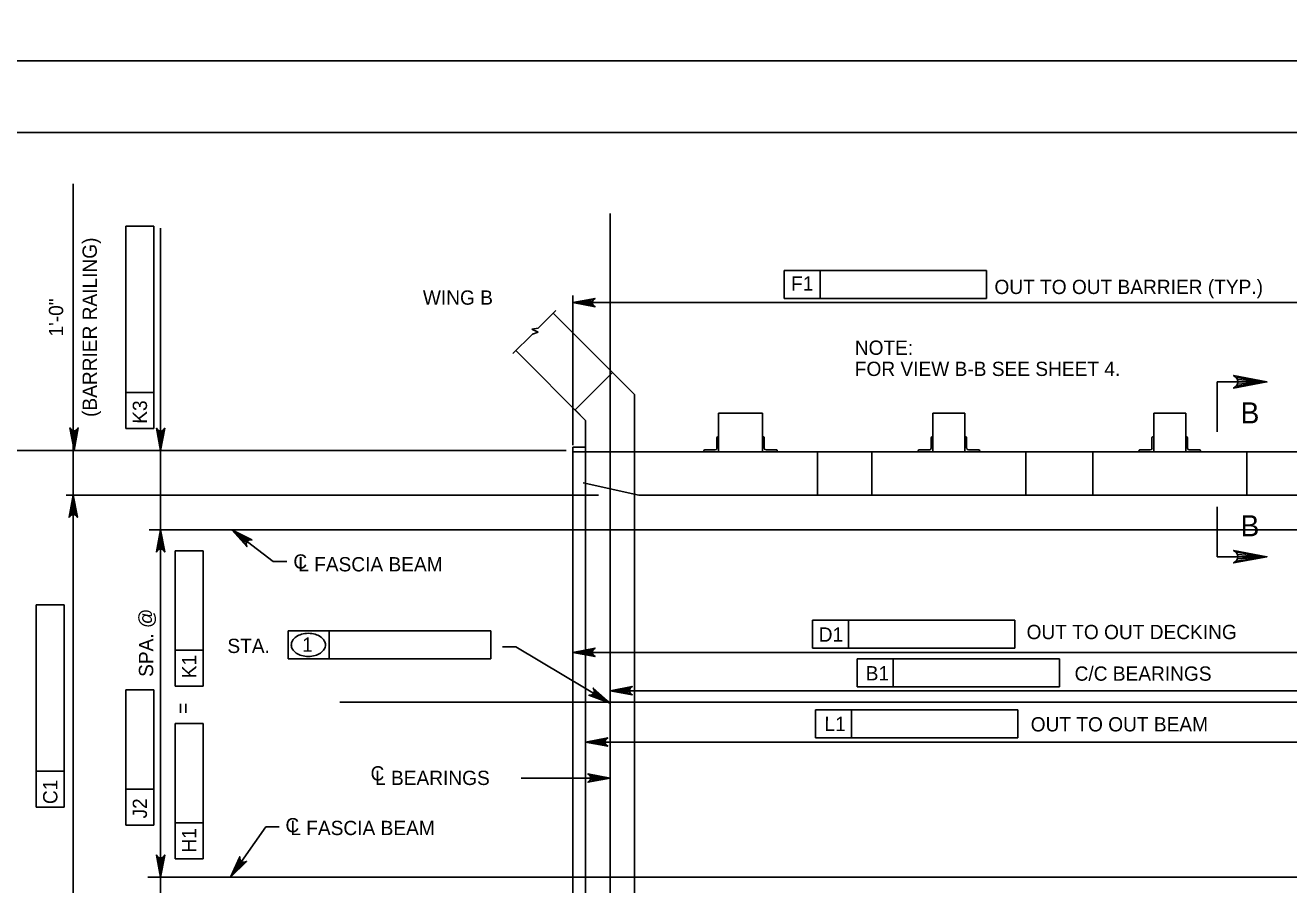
# Model space of a CAD drawing. Extents: x 638263 to 640391, y 293683 to 298655.
# Drawn here: x 638498.6 to 638763.9, y 294698.5 to 294879 of the extents above; entities that cross this region are included whole.
import ezdxf

# ---------------------------------------------------------------- set-up
doc = ezdxf.new("R2010")
doc.units = 0
for name, color, linetype in [('2', 7, 'Continuous'), ('3', 7, 'Continuous'), ('4', 7, 'Continuous'), ('PLT-BNDY', 7, 'Continuous')]:
    doc.layers.add(name, color=color, linetype=linetype)

msp = doc.modelspace()

# ---------------------------------------------------------------- linework, layer by layer
at = {"layer": '2'}
for p, q in [((638475.46, 294856.46), (639261.46, 294856.46)), ((638626.57, 294801.41), (638609.48, 294818.49)), ((638616.27, 294795.97), (638601.61, 294810.62)), ((638614.07, 294798.17), (638621.94, 294806.04)), ((638748.83, 294804.07), (638748.83, 294793.58)), ((638748.83, 294804.07), (638759.31, 294804.07)), ((638626.57, 294801.41), (638626.57, 294789.4)), ((638616.27, 294795.97), (638614.07, 294798.17)), ((638644.19, 294797.49), (638653.42, 294797.49)), ((638644.19, 294797.49), (638644.19, 294789.4)), ((638653.42, 294797.49), (638653.42, 294789.4)), ((638695.91, 294797.49), (638689.18, 294797.49)), ((638689.18, 294797.49), (638689.18, 294789.4)), ((638695.91, 294797.49), (638695.91, 294789.4)), ((638742.27, 294797.49), (638735.54, 294797.49)), ((638735.54, 294797.49), (638735.54, 294789.4)), ((638742.27, 294797.49), (638742.27, 294789.4)), ((638616.27, 294789.4), (638616.27, 294795.97)), ((638643.82, 294792.31), (638643.82, 294790.13)), ((638644, 294792.49), (638644.19, 294792.49)), ((638644.19, 294792.49), (638644.19, 294789.4)), ((638653.6, 294792.49), (638653.42, 294792.49)), ((638653.42, 294792.49), (638653.42, 294789.4)), ((638653.79, 294792.31), (638653.79, 294790.13)), ((638688.82, 294792.31), (638688.82, 294790.13)), ((638689, 294792.49), (638689.18, 294792.49)), ((638689.18, 294792.49), (638689.18, 294789.4)), ((638696.09, 294792.49), (638695.91, 294792.49)), ((638695.91, 294792.49), (638695.91, 294789.4)), ((638696.27, 294792.31), (638696.27, 294790.13)), ((638735.18, 294792.31), (638735.18, 294790.13)), ((638735.36, 294792.49), (638735.54, 294792.49)), ((638735.54, 294792.49), (638735.54, 294789.4)), ((638742.45, 294792.49), (638742.27, 294792.49)), ((638742.27, 294792.49), (638742.27, 294789.4)), ((638742.63, 294792.31), (638742.63, 294790.13)), ((638613.6, 294682.15), (638613.6, 294790.36)), ((638613.6, 294790.36), (638616.27, 294790.36)), ((638613.6, 294789.4), (638816.67, 294789.4)), ((638616.27, 294683.1), (638616.27, 294789.4)), ((638626.57, 294683.1), (638626.57, 294789.4)), ((638641.1, 294789.59), (638641.1, 294789.4)), ((638644.19, 294789.4), (638641.1, 294789.4)), ((638641.28, 294789.77), (638643.46, 294789.77)), ((638644.19, 294789.4), (638653.42, 294789.4)), ((638653.42, 294789.4), (638656.51, 294789.4)), ((638656.33, 294789.77), (638654.15, 294789.77)), ((638656.51, 294789.59), (638656.51, 294789.4)), ((638664.97, 294789.4), (638664.97, 294780.28)), ((638676.37, 294789.4), (638676.37, 294780.28)), ((638686.09, 294789.59), (638686.09, 294789.4)), ((638689.18, 294789.4), (638686.09, 294789.4)), ((638686.27, 294789.77), (638688.45, 294789.77)), ((638695.91, 294789.4), (638689.18, 294789.4)), ((638695.91, 294789.4), (638699, 294789.4)), ((638734.33, 294789.4), (638695.91, 294789.4)), ((638698.82, 294789.77), (638696.64, 294789.77)), ((638699, 294789.59), (638699, 294789.4)), ((638708.71, 294789.4), (638708.71, 294780.28)), ((638722.74, 294789.4), (638722.74, 294780.28)), ((638732.45, 294789.59), (638732.45, 294789.4)), ((638735.54, 294789.4), (638732.45, 294789.4)), ((638732.64, 294789.77), (638734.82, 294789.77)), ((638743.53, 294789.4), (638734.29, 294789.4)), ((638742.27, 294789.4), (638735.54, 294789.4)), ((638742.27, 294789.4), (638745.36, 294789.4)), ((638745.18, 294789.77), (638743, 294789.77)), ((638745.36, 294789.59), (638745.36, 294789.4)), ((638755.08, 294789.4), (638755.08, 294780.28)), ((638615.77, 294782.89), (638627.45, 294780.28)), ((638660.75, 294780.28), (638627.45, 294780.28)), ((638658.08, 294780.28), (638804.99, 294780.28)), ((638748.83, 294767.34), (638748.83, 294777.82)), ((638748.83, 294767.34), (638759.31, 294767.34))]:
    msp.add_line(p, q, dxfattribs=at)
for points in [[(638759.31, 294804.07), (638752.32, 294802.76), (638752.86, 294803.13), (638753.14, 294803.6), (638753.22, 294804.07), (638753.14, 294804.53), (638752.86, 294805), (638752.32, 294805.38), (638759.31, 294804.07), (638752.86, 294805), (638753.14, 294804.53), (638759.31, 294804.07), (638753.22, 294804.07), (638753.14, 294803.6), (638759.31, 294804.07), (638752.86, 294803.13)], [(638759.31, 294767.34), (638752.32, 294768.64), (638752.86, 294768.27), (638753.14, 294767.8), (638753.22, 294767.34), (638753.14, 294766.87), (638752.86, 294766.4), (638752.32, 294766.03), (638759.31, 294767.34), (638752.86, 294766.4), (638753.14, 294766.87), (638759.31, 294767.34), (638753.22, 294767.34), (638753.14, 294767.8), (638759.31, 294767.34), (638752.86, 294768.27)]]:
    msp.add_lwpolyline(points, dxfattribs=at)
for centre, radius, start, end in [((638644, 294792.31), 0.182, 90, 179.9984), ((638653.6, 294792.31), 0.182, 0.0016, 90), ((638689, 294792.31), 0.182, 90, 179.9984), ((638696.09, 294792.31), 0.182, 0.0016, 90), ((638735.36, 294792.31), 0.182, 90, 179.9984), ((638742.45, 294792.31), 0.182, 0.0016, 90), ((638641.28, 294789.59), 0.182, 90, 179.9984), ((638643.46, 294790.13), 0.364, 270, 359.9984), ((638654.15, 294790.13), 0.364, 180.0016, 270), ((638656.33, 294789.59), 0.182, 0.0016, 90), ((638686.27, 294789.59), 0.182, 90, 179.9984), ((638688.45, 294790.13), 0.364, 270, 359.9984), ((638696.64, 294790.13), 0.364, 180.0016, 270), ((638698.82, 294789.59), 0.182, 0.0016, 90), ((638732.64, 294789.59), 0.182, 90, 179.9984), ((638734.82, 294790.13), 0.364, 270, 359.9984), ((638743, 294790.13), 0.364, 180.0016, 270), ((638745.18, 294789.59), 0.182, 0.0016, 90)]:
    msp.add_arc(centre, radius, start, end, dxfattribs=at)
at = {"layer": '3'}
for p, q in [((638621.42, 294636.37), (638621.42, 294839.45)), ((638606.3, 294815.31), (638610.04, 294819.05)), ((638606.3, 294815.31), (638605.01, 294815.16)), ((638601.01, 294810.02), (638605.09, 294814.1)), ((638605.01, 294815.16), (638606.34, 294814.49)), ((638606.34, 294814.49), (638605.09, 294814.1))]:
    msp.add_line(p, q, dxfattribs=at)
at = {"layer": '4'}
for p, q in [((638508.72, 294845.63), (638508.72, 294625.42)), ((638525.64, 294836.77), (638519.74, 294836.77)), ((638519.74, 294801.82), (638519.74, 294836.77)), ((638525.64, 294794.25), (638525.64, 294836.77)), ((638527.05, 294795.34), (638527.05, 294836.34)), ((638657.94, 294827.46), (638665.5, 294827.46)), ((638657.94, 294827.46), (638657.94, 294821.55)), ((638665.5, 294827.46), (638665.5, 294821.55)), ((638665.5, 294827.46), (638700.46, 294827.46)), ((638700.46, 294827.46), (638700.46, 294821.55)), ((638613.6, 294790.8), (638613.6, 294822.22)), ((638613.6, 294820.7), (638816.67, 294820.7)), ((638657.94, 294821.55), (638700.46, 294821.55)), ((638519.74, 294794.25), (638519.74, 294801.82)), ((638525.64, 294801.81), (638519.74, 294801.82)), ((638519.74, 294794.25), (638525.64, 294794.25)), ((638527.05, 294792.51), (638527.05, 294795.34)), ((638612.16, 294789.67), (638493.53, 294789.67)), ((638527.05, 294683.37), (638527.05, 294789.67)), ((638618.96, 294780.28), (638507.24, 294780.28)), ((638825.07, 294773.02), (638524.65, 294773.02)), ((638542, 294773.02), (638550.7, 294766.33)), ((638536, 294768.55), (638530.1, 294768.55)), ((638530.1, 294747.71), (638530.1, 294768.55)), ((638536, 294740.14), (638536, 294768.55)), ((638550.7, 294766.33), (638553.53, 294766.33)), ((638506.83, 294757.25), (638500.93, 294757.26)), ((638500.93, 294722.3), (638500.93, 294757.26)), ((638506.83, 294714.73), (638506.83, 294757.25)), ((638553.83, 294745.89), (638553.83, 294751.8)), ((638553.83, 294751.8), (638561.4, 294751.8)), ((638561.4, 294751.8), (638596.35, 294751.8)), ((638562.47, 294745.89), (638562.47, 294751.8)), ((638596.35, 294751.8), (638596.35, 294745.89)), ((638663.88, 294754.02), (638671.44, 294754.02)), ((638663.88, 294754.02), (638663.88, 294748.11)), ((638671.44, 294754.02), (638671.44, 294748.11)), ((638671.44, 294754.02), (638706.4, 294754.02)), ((638706.4, 294754.02), (638706.4, 294748.11)), ((638536, 294747.7), (638530.1, 294747.71)), ((638530.1, 294740.15), (638530.1, 294747.71)), ((638601.64, 294748.45), (638598.81, 294748.45)), ((638621.42, 294736.59), (638601.64, 294748.45)), ((638613.6, 294747.26), (638816.67, 294747.26)), ((638663.88, 294748.11), (638706.4, 294748.11)), ((638596.35, 294745.89), (638553.83, 294745.89)), ((638673.26, 294745.89), (638715.78, 294745.89)), ((638673.26, 294745.89), (638673.26, 294739.99)), ((638680.83, 294745.89), (638680.83, 294739.99)), ((638715.78, 294745.89), (638715.78, 294739.99)), ((638525.64, 294739.37), (638519.74, 294739.38)), ((638519.74, 294718.54), (638519.74, 294739.38)), ((638525.64, 294710.97), (638525.64, 294739.37)), ((638530.1, 294740.15), (638536, 294740.14)), ((638621.42, 294739.21), (638809, 294739.21)), ((638673.26, 294739.99), (638715.78, 294739.99)), ((638859.2, 294736.83), (638564.7, 294736.83)), ((638664.51, 294735.18), (638672.07, 294735.18)), ((638664.51, 294735.18), (638664.51, 294729.28)), ((638672.07, 294735.18), (638672.07, 294729.28)), ((638672.07, 294735.18), (638707.03, 294735.18)), ((638707.03, 294735.18), (638707.03, 294729.28)), ((638536, 294732.32), (638530.1, 294732.32)), ((638530.1, 294711.48), (638530.1, 294732.32)), ((638536, 294703.91), (638536, 294732.32)), ((638616.27, 294728.43), (638814.15, 294728.43)), ((638664.51, 294729.28), (638707.03, 294729.28)), ((638500.93, 294714.74), (638500.93, 294722.3)), ((638506.83, 294722.3), (638500.93, 294722.3)), ((638602.74, 294720.86), (638621.42, 294720.86)), ((638519.74, 294710.98), (638519.74, 294718.54)), ((638525.64, 294718.53), (638519.74, 294718.54)), ((638500.93, 294714.74), (638506.83, 294714.73)), ((638519.74, 294710.98), (638525.64, 294710.97)), ((638530.1, 294703.92), (638530.1, 294711.48)), ((638536, 294711.47), (638530.1, 294711.48)), ((638541.71, 294700.03), (638549.14, 294710.64)), ((638549.14, 294710.64), (638551.97, 294710.64)), ((638530.1, 294703.92), (638536, 294703.91)), ((638825.07, 294700.03), (638524.35, 294700.03))]:
    msp.add_line(p, q, dxfattribs=at)
for points in [[(638613.6, 294820.7), (638618.26, 294821.58), (638617.9, 294821.33), (638617.72, 294821.02), (638617.66, 294820.7), (638617.72, 294820.39), (638617.9, 294820.08), (638618.26, 294819.83), (638613.6, 294820.7), (638617.9, 294820.08), (638617.72, 294820.39), (638613.6, 294820.7), (638617.66, 294820.7), (638617.72, 294821.02), (638613.6, 294820.7), (638617.9, 294821.33)], [(638508.87, 294789.74), (638508, 294794.4), (638508.25, 294794.04), (638508.56, 294793.86), (638508.87, 294793.81), (638509.19, 294793.86), (638509.5, 294794.04), (638509.75, 294794.4), (638508.87, 294789.74), (638509.5, 294794.04), (638509.19, 294793.86), (638508.87, 294789.74), (638508.87, 294793.81), (638508.56, 294793.86), (638508.87, 294789.74), (638508.25, 294794.04)], [(638527.05, 294789.67), (638526.18, 294794.33), (638526.43, 294793.97), (638526.74, 294793.79), (638527.05, 294793.73), (638527.36, 294793.79), (638527.68, 294793.97), (638527.92, 294794.33), (638527.05, 294789.67), (638527.68, 294793.97), (638527.36, 294793.79), (638527.05, 294789.67), (638527.05, 294793.73), (638526.74, 294793.79), (638527.05, 294789.67), (638526.43, 294793.97)], [(638508.72, 294780.28), (638509.59, 294775.62), (638509.35, 294775.98), (638509.03, 294776.17), (638508.72, 294776.22), (638508.41, 294776.17), (638508.1, 294775.98), (638507.85, 294775.62), (638508.72, 294780.28), (638508.1, 294775.98), (638508.41, 294776.17), (638508.72, 294780.28), (638508.72, 294776.22), (638509.03, 294776.17), (638508.72, 294780.28), (638509.35, 294775.98)], [(638527.05, 294773.02), (638527.92, 294768.36), (638527.68, 294768.72), (638527.36, 294768.9), (638527.05, 294768.96), (638526.74, 294768.9), (638526.43, 294768.72), (638526.18, 294768.36), (638527.05, 294773.02), (638526.43, 294768.72), (638526.74, 294768.9), (638527.05, 294773.02), (638527.05, 294768.96), (638527.36, 294768.9), (638527.05, 294773.02), (638527.68, 294768.72)], [(638542, 294773.02), (638546.23, 294770.87), (638545.79, 294770.89), (638545.45, 294770.76), (638545.22, 294770.54), (638545.07, 294770.26), (638545.03, 294769.9), (638545.16, 294769.48), (638542, 294773.02), (638545.03, 294769.9), (638545.07, 294770.26), (638542, 294773.02), (638545.22, 294770.54), (638545.45, 294770.76), (638542, 294773.02), (638545.79, 294770.89)], [(638613.6, 294747.26), (638618.26, 294748.14), (638617.9, 294747.89), (638617.72, 294747.58), (638617.66, 294747.26), (638617.72, 294746.95), (638617.9, 294746.64), (638618.26, 294746.39), (638613.6, 294747.26), (638617.9, 294746.64), (638617.72, 294746.95), (638613.6, 294747.26), (638617.66, 294747.26), (638617.72, 294747.58), (638613.6, 294747.26), (638617.9, 294747.89)], [(638621.42, 294736.59), (638616.97, 294738.24), (638617.41, 294738.27), (638617.73, 294738.44), (638617.93, 294738.68), (638618.05, 294738.98), (638618.05, 294739.34), (638617.87, 294739.74), (638621.42, 294736.59), (638618.05, 294739.34), (638618.05, 294738.98), (638621.42, 294736.59), (638617.93, 294738.68), (638617.73, 294738.44), (638621.42, 294736.59), (638617.41, 294738.27)], [(638621.42, 294739.21), (638626.08, 294740.08), (638625.72, 294739.83), (638625.54, 294739.52), (638625.48, 294739.21), (638625.54, 294738.9), (638625.72, 294738.58), (638626.08, 294738.34), (638621.42, 294739.21), (638625.72, 294738.58), (638625.54, 294738.9), (638621.42, 294739.21), (638625.48, 294739.21), (638625.54, 294739.52), (638621.42, 294739.21), (638625.72, 294739.83)], [(638616.27, 294728.43), (638620.93, 294729.3), (638620.58, 294729.06), (638620.39, 294728.74), (638620.34, 294728.43), (638620.39, 294728.12), (638620.58, 294727.81), (638620.93, 294727.56), (638616.27, 294728.43), (638620.58, 294727.81), (638620.39, 294728.12), (638616.27, 294728.43), (638620.34, 294728.43), (638620.39, 294728.74), (638616.27, 294728.43), (638620.58, 294729.06)], [(638621.42, 294720.86), (638616.76, 294719.98), (638617.12, 294720.23), (638617.3, 294720.55), (638617.36, 294720.86), (638617.3, 294721.17), (638617.12, 294721.48), (638616.76, 294721.73), (638621.42, 294720.86), (638617.12, 294721.48), (638617.3, 294721.17), (638621.42, 294720.86), (638617.36, 294720.86), (638617.3, 294720.55), (638621.42, 294720.86), (638617.12, 294720.23)], [(638527.05, 294700.03), (638526.18, 294704.69), (638526.43, 294704.33), (638526.74, 294704.14), (638527.05, 294704.09), (638527.36, 294704.14), (638527.68, 294704.33), (638527.92, 294704.69), (638527.05, 294700.03), (638527.68, 294704.33), (638527.36, 294704.14), (638527.05, 294700.03), (638527.05, 294704.09), (638526.74, 294704.14), (638527.05, 294700.03), (638526.43, 294704.33)], [(638541.71, 294700.03), (638543.67, 294704.35), (638543.67, 294703.91), (638543.82, 294703.58), (638544.04, 294703.36), (638544.33, 294703.22), (638544.69, 294703.19), (638545.1, 294703.35), (638541.71, 294700.03), (638544.69, 294703.19), (638544.33, 294703.22), (638541.71, 294700.03), (638544.04, 294703.36), (638543.82, 294703.58), (638541.71, 294700.03), (638543.67, 294703.91)]]:
    msp.add_lwpolyline(points, dxfattribs=at)
for centre, radius, start, end in [((638556.16, 294748.83), 1.68, 148.5507, 180), ((638557.07, 294748.27), 2.75, 124.109, 148.5507), ((638557.67, 294747.39), 3.82, 105.6708, 124.109), ((638558.06, 294745.99), 5.27, 90, 105.6708), ((638558.06, 294745.99), 5.27, 74.3292, 90), ((638558.46, 294747.39), 3.82, 55.891, 74.3292), ((638559.06, 294748.27), 2.75, 31.4493, 55.891), ((638559.97, 294748.83), 1.68, 0, 31.4493), ((638556.16, 294748.83), 1.68, 180, 211.4493), ((638557.07, 294749.39), 2.75, 211.4493, 235.891), ((638557.67, 294750.28), 3.82, 235.891, 254.3292), ((638558.06, 294751.68), 5.27, 254.3292, 270), ((638558.06, 294751.68), 5.27, 270, 285.6708), ((638558.46, 294750.28), 3.82, 285.6708, 304.109), ((638559.06, 294749.39), 2.75, 304.109, 328.5507), ((638559.97, 294748.83), 1.68, 328.5507, 0)]:
    msp.add_arc(centre, radius, start, end, dxfattribs=at)
at = {"layer": 'PLT-BNDY'}
for points in [[(638435.46, 295465.46), (639276.46, 295465.46), (639276.46, 294871.46), (638435.46, 294871.46)], [(638435.46, 294871.46), (639276.46, 294871.46), (639276.46, 294277.46), (638435.46, 294277.46)]]:
    msp.add_lwpolyline(points, close=True, dxfattribs=at)

# ---------------------------------------------------------------- texts
at = {"layer": '4'}
for s, height, rotation, p in [('(BARRIER RAILING)', 3, 90, (638513.66, 294796.7)), ('F1', 3, 359.9382, (638659.41, 294823.22)), ('1\'-0"', 3, 90, (638506.59, 294813.59)), ('K3', 3, 89.9382, (638524.19, 294795.27)), ('B', 4.43, 360, (638753.77, 294795.34)), ('SPA. @', 3, 90, (638525.49, 294742.11)), ('D1', 3, 359.9382, (638665.21, 294749.5)), ('K1', 3, 89.9382, (638534.55, 294741.82)), ('B1', 3, 359.9382, (638675.07, 294741.37)), ('=', 3, 90, (638533.22, 294734.35)), ('L1', 3, 359.9382, (638666.42, 294730.73)), ('C1', 3, 89.9382, (638505.38, 294715.39)), ('J2', 3, 89.9382, (638524.19, 294712.37)), ('H1', 3, 89.9382, (638534.55, 294705.21))]:
    msp.add_text(s, height=height, rotation=rotation, dxfattribs=at).set_placement(p)
for s, height, p in [('WING B', 3, (638582.11, 294820.27)), ('OUT TO OUT BARRIER (TYP.)', 3, (638702.1, 294822.51)), ('NOTE:', 3, (638672.79, 294809.74)), ('FOR VIEW B-B SEE SHEET 4.', 3, (638672.79, 294805.3)), ('B', 4.43, (638753.77, 294771.63)), ('C', 3, (638554.92, 294764.84)), ('L FASCIA BEAM', 3, (638555.94, 294764.26)), ('OUT TO OUT DECKING', 3, (638708.85, 294750.03)), ('STA.', 3, (638541.07, 294747.12)), ('1', 3, (638556.76, 294747.38)), ('C/C BEARINGS', 3, (638718.93, 294741.3)), ('OUT TO OUT BEAM', 3, (638709.72, 294730.65)), ('C', 3, (638571.12, 294720.35)), ('L BEARINGS', 3, (638572.07, 294719.4)), ('C', 3, (638553.26, 294709.46)), ('L FASCIA BEAM', 3, (638554.28, 294708.88))]:
    msp.add_text(s, height=height, dxfattribs=at).set_placement(p)

doc.saveas('drawing.dxf')
